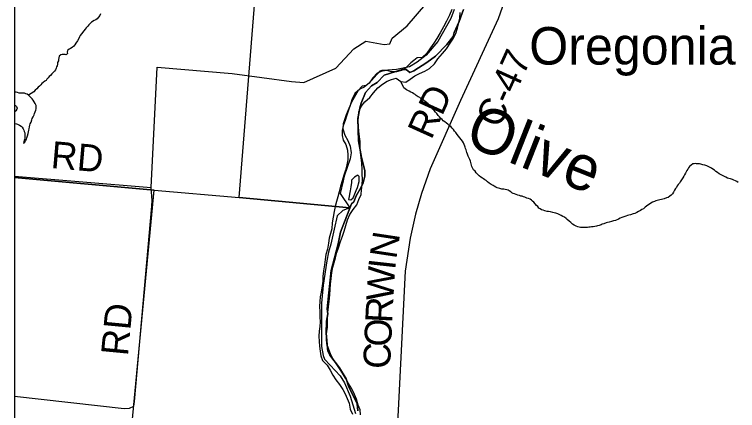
# Model space of a CAD drawing. Extents: x 0.4 to 34.4, y -2.1 to 19.9.
# Drawn here: x 3 to 4.522, y 15.102 to 15.936 of the extents above; entities that cross this region are included whole.
import ezdxf

# ---------------------------------------------------------------- set-up
doc = ezdxf.new("R2010")
doc.units = 0
for name, color, linetype in [('GM_X_County', 7, 'Continuous'), ('GM_X_County_Road', 7, 'Continuous'), ('GM_X_County_Road_Text', 7, 'Continuous'), ('GM_X_Major_River', 7, 'Continuous'), ('GM_X_Minor_Lake', 7, 'Continuous'), ('GM_X_Minor_River', 7, 'Continuous'), ('GM_X_Minor_River_Text', 7, 'Continuous'), ('GM_X_Section', 7, 'Continuous'), ('GM_X_Township', 7, 'Continuous'), ('GM_X_Township_Road', 7, 'Continuous'), ('GM_X_Township_Road_Text', 7, 'Continuous'), ('GM_X_Unincorporated_Text', 7, 'Continuous'), ('SH_Data', 7, 'Continuous')]:
    doc.layers.add(name, color=color, linetype=linetype)

msp = doc.modelspace()

# ---------------------------------------------------------------- linework, layer by layer
at = {"layer": 'GM_X_County'}
msp.add_lwpolyline([(9.8001, 15.3423), (9.8001, 18.8357), (3.0001, 18.8357), (3.0001, 12.0357), (9.5074, 12.0357)], dxfattribs=at)
at = {"layer": 'GM_X_County_Road'}
msp.add_lwpolyline([(4.0921, 16.025), (4.075, 16.0392), (4.0559, 16.0588), (4.042, 16.007), (4.0308, 15.9623), (4.0179, 15.9268), (3.9392, 15.755), (3.8752, 15.6108), (3.8571, 15.559), (3.8445, 15.5155), (3.8329, 15.4647), (3.8225, 15.3954), (3.798, 14.9078), (3.7927, 14.8467), (3.7874, 14.8168), (3.7683, 14.7707), (3.7416, 14.7273), (3.683, 14.6568)], dxfattribs=at)
at = {"layer": 'GM_X_Major_River'}
for points in [[(3.6597, 15.3086), (3.6614, 15.3207), (3.6623, 15.3321), (3.664, 15.3457), (3.6646, 15.3579), (3.6655, 15.3681), (3.6664, 15.3802), (3.6682, 15.3927), (3.6702, 15.4037), (3.673, 15.4135), (3.6758, 15.4237), (3.6787, 15.435), (3.6827, 15.4467), (3.6866, 15.4581), (3.6906, 15.4694), (3.6942, 15.4796), (3.6978, 15.4916), (3.7014, 15.5037), (3.7061, 15.515), (3.7131, 15.5252), (3.7205, 15.5353), (3.7252, 15.5462), (3.7299, 15.5568), (3.7308, 15.567), (3.7317, 15.5776), (3.7323, 15.589), (3.7321, 15.5996), (3.7322, 15.6098), (3.7313, 15.6231), (3.7296, 15.6342), (3.7282, 15.6463), (3.7277, 15.6585), (3.7274, 15.6687), (3.7265, 15.6786), (3.7251, 15.6904), (3.7245, 15.6999), (3.7236, 15.712), (3.7246, 15.7306), (3.7297, 15.7419), (3.7375, 15.752), (3.7478, 15.761), (3.7556, 15.7711), (3.7649, 15.7812), (3.7748, 15.7894), (3.7844, 15.7953), (3.794, 15.7989), (3.8035, 15.8014), (3.8136, 15.7944), (3.8235, 15.7932), (3.8331, 15.7998), (3.8431, 15.8069), (3.8526, 15.8113), (3.8637, 15.8164), (3.874, 15.8223), (3.8841, 15.832), (3.8914, 15.8425), (3.9007, 15.8534), (3.9092, 15.8631), (3.9174, 15.8755), (3.924, 15.8857), (3.9291, 15.8954), (3.9327, 15.9068), (3.9351, 15.9185), (3.9372, 15.9283), (3.9381, 15.9401)], [(3.9207, 15.946), (3.9156, 15.934), (3.9097, 15.9215), (3.9031, 15.9095), (3.8961, 15.8971)], [(3.8961, 15.8971), (3.8894, 15.8854), (3.8828, 15.8757), (3.8758, 15.8652), (3.8677, 15.8543), (3.8581, 15.8453), (3.8478, 15.8444), (3.8408, 15.8387), (3.8344, 15.834), (3.824, 15.8235), (3.8144, 15.8176), (3.8041, 15.8151), (3.7938, 15.8152), (3.7836, 15.8181), (3.7738, 15.8167), (3.7634, 15.8119), (3.7545, 15.8022), (3.7468, 15.7909), (3.7364, 15.7831), (3.7269, 15.7787), (3.7168, 15.7694), (3.7102, 15.7562), (3.7066, 15.7441), (3.7034, 15.7343), (3.6998, 15.7238), (3.6962, 15.7128), (3.6919, 15.7015), (3.6895, 15.6917), (3.6897, 15.6811), (3.6922, 15.6715), (3.6974, 15.662), (3.701, 15.6505), (3.7016, 15.6395), (3.7018, 15.6297), (3.6997, 15.6191), (3.6969, 15.6081), (3.6933, 15.5976), (3.6897, 15.5859), (3.6865, 15.5745), (3.6833, 15.5624), (3.6809, 15.5518), (3.6777, 15.542), (3.6748, 15.5315), (3.6732, 15.5209), (3.6707, 15.5091), (3.669, 15.4974), (3.6681, 15.4849), (3.6656, 15.4751), (3.6628, 15.4653), (3.6608, 15.4543), (3.6587, 15.4418), (3.6558, 15.4305), (3.6538, 15.4203), (3.6525, 15.4089), (3.6507, 15.396), (3.6494, 15.3843), (3.6489, 15.3748), (3.6476, 15.3646), (3.6455, 15.3513), (3.6435, 15.3415), (3.6429, 15.3316), (3.6424, 15.321), (3.6426, 15.3097), (3.6428, 15.299), (3.6434, 15.2888), (3.6429, 15.2793), (3.6416, 15.2691), (3.6407, 15.2588), (3.6413, 15.2478), (3.6422, 15.2376), (3.6436, 15.2269), (3.645, 15.2174), (3.6486, 15.2075), (3.6583, 15.1979), (3.6646, 15.1872), (3.6702, 15.1764), (3.6768, 15.1669), (3.6843, 15.1569), (3.691, 15.1469), (3.6961, 15.1373), (3.7005, 15.1274), (3.7045, 15.1175), (3.707, 15.1053), (3.7114, 15.0946)], [(3.7226, 15.5979), (3.716, 15.5934), (3.7098, 15.5868), (3.7094, 15.5821), (3.7081, 15.5727), (3.7069, 15.5643), (3.7056, 15.5579), (3.7044, 15.5526), (3.7035, 15.5462), (3.7081, 15.5454), (3.7127, 15.5502), (3.7151, 15.5551)], [(3.7151, 15.5551), (3.719, 15.5653), (3.7221, 15.5713), (3.7254, 15.5842), (3.7255, 15.5948), (3.7226, 15.5979)], [(3.7281, 15.0932), (3.7275, 15.1035), (3.7238, 15.1138), (3.7199, 15.126), (3.7158, 15.1363), (3.7103, 15.1481), (3.7033, 15.1592), (3.6966, 15.1703), (3.6907, 15.1811), (3.684, 15.1906), (3.6774, 15.201), (3.6703, 15.2117), (3.6651, 15.2213), (3.6615, 15.2308), (3.6579, 15.243), (3.6569, 15.2533), (3.6571, 15.2639), (3.6588, 15.2779), (3.659, 15.2878), (3.6587, 15.2984), (3.6597, 15.3086)]]:
    msp.add_lwpolyline(points, dxfattribs=at)
at = {"layer": 'GM_X_Minor_Lake'}
for points in [[(3.0299, 15.7662), (3.0269, 15.7682), (3.0243, 15.769), (3.0216, 15.7698), (3.0182, 15.7702), (3.0152, 15.7703), (3.0125, 15.7703), (3.0098, 15.7704), (3.0064, 15.7712), (3.0034, 15.772), (3.0007, 15.7725), (3.0001, 15.7726)], [(3.0001, 15.7062), (3.0008, 15.7063), (3.0042, 15.7054), (3.0068, 15.7046), (3.0106, 15.703), (3.014, 15.7007), (3.0166, 15.6984), (3.0181, 15.6953), (3.0195, 15.6922), (3.0206, 15.6895), (3.0217, 15.6868), (3.022, 15.6842), (3.0219, 15.6815), (3.0222, 15.6758), (3.0214, 15.6724), (3.0201, 15.6678), (3.0189, 15.6648), (3.022, 15.667), (3.0236, 15.6701), (3.0256, 15.6731), (3.0264, 15.6765), (3.0276, 15.6806), (3.0289, 15.6856), (3.0297, 15.689), (3.0306, 15.692), (3.0314, 15.695), (3.0319, 15.6996), (3.0327, 15.703), (3.0332, 15.7057), (3.0351, 15.709), (3.0368, 15.714), (3.0376, 15.717), (3.0392, 15.7204), (3.0416, 15.7249), (3.042, 15.7276), (3.0436, 15.731), (3.0449, 15.7347), (3.0457, 15.7374), (3.0457, 15.7401), (3.0455, 15.7443), (3.044, 15.7481), (3.0418, 15.7519), (3.0396, 15.7554), (3.0374, 15.7585), (3.0299, 15.7662)], [(3.0001, 15.7452), (3.002, 15.7443), (3.0046, 15.742), (3.0057, 15.7389), (3.0049, 15.7362), (3.0033, 15.7328), (3.0006, 15.731), (3.0001, 15.7308)]]:
    msp.add_lwpolyline(points, dxfattribs=at)
at = {"layer": 'GM_X_Minor_River'}
for points in [[(3.1813, 15.9373), (3.1801, 15.9339), (3.177, 15.9298), (3.1742, 15.9268), (3.1711, 15.9246), (3.168, 15.9228), (3.1626, 15.9194), (3.1599, 15.9172), (3.1568, 15.9138), (3.1544, 15.9108), (3.1509, 15.9078), (3.1489, 15.9048), (3.1458, 15.9011), (3.1415, 15.8947), (3.1387, 15.8913), (3.1371, 15.8887), (3.1355, 15.8853), (3.1328, 15.88), (3.1292, 15.8755), (3.1272, 15.8721), (3.1249, 15.8691), (3.1218, 15.8661), (3.1179, 15.8639), (3.1152, 15.8625), (3.1117, 15.8602), (3.1113, 15.8561), (3.1116, 15.8534), (3.1092, 15.8508), (3.1066, 15.8512), (3.1031, 15.8513), (3.1005, 15.8513), (3.0974, 15.851), (3.0943, 15.848), (3.0934, 15.8442), (3.093, 15.8408), (3.0925, 15.8381), (3.0909, 15.8344), (3.0905, 15.8309), (3.0897, 15.8279), (3.0888, 15.8253), (3.088, 15.8226), (3.0864, 15.8192), (3.0844, 15.8166), (3.0817, 15.8136), (3.079, 15.811), (3.0759, 15.8076), (3.0731, 15.805), (3.0712, 15.8024), (3.0684, 15.7998), (3.0668, 15.7971), (3.0638, 15.7953), (3.0606, 15.7927), (3.0579, 15.7904), (3.0556, 15.7878), (3.0525, 15.7852), (3.0501, 15.7826), (3.047, 15.7796), (3.0439, 15.7766), (3.0408, 15.7733), (3.0299, 15.7662)], [(3.9093, 15.7071), (3.9056, 15.7095), (3.9026, 15.7118), (3.9, 15.7149), (3.8974, 15.7168), (3.8944, 15.7203), (3.8922, 15.723), (3.8888, 15.7273), (3.8862, 15.7304), (3.8836, 15.7335), (3.881, 15.7362), (3.8777, 15.7404), (3.8758, 15.7431), (3.8732, 15.7447), (3.8706, 15.7478), (3.8676, 15.7505), (3.8646, 15.7528), (3.8612, 15.7552), (3.8582, 15.7571), (3.8556, 15.7587), (3.853, 15.7607), (3.85, 15.7626), (3.8458, 15.7654), (3.8432, 15.7673), (3.8406, 15.7689), (3.8376, 15.7708), (3.8342, 15.7724), (3.8308, 15.7744), (3.8281, 15.7759), (3.8251, 15.7771), (3.8221, 15.7795), (3.8195, 15.7814), (3.8136, 15.7944)], [(4.1885, 15.4881), (4.1858, 15.4889), (4.1821, 15.4905), (4.1783, 15.4925), (4.1749, 15.4948), (4.1708, 15.498), (4.1674, 15.5007), (4.1637, 15.5042), (4.1611, 15.5065), (4.1577, 15.5089), (4.1543, 15.5108), (4.1505, 15.5128), (4.1464, 15.5148), (4.1437, 15.516), (4.1396, 15.5176), (4.1358, 15.5184), (4.1331, 15.5192), (4.1286, 15.5201), (4.124, 15.5209), (4.121, 15.5213), (4.1164, 15.5222), (4.1126, 15.5238), (4.1096, 15.525), (4.1066, 15.5265), (4.104, 15.5285), (4.1014, 15.5316), (4.0988, 15.5339), (4.0958, 15.5374), (4.0932, 15.5405), (4.0906, 15.5428), (4.088, 15.5448), (4.0853, 15.5471), (4.0819, 15.5483), (4.0785, 15.5495), (4.0744, 15.5511), (4.0713, 15.5523), (4.0687, 15.5531), (4.066, 15.5535), (4.063, 15.5547), (4.0596, 15.5556), (4.0562, 15.5568), (4.0528, 15.558), (4.0498, 15.5592), (4.0471, 15.5604), (4.0445, 15.5623), (4.0415, 15.5643), (4.0389, 15.5658), (4.0362, 15.567), (4.0332, 15.5675), (4.0301, 15.5679), (4.0256, 15.5684), (4.0214, 15.5692), (4.0187, 15.57), (4.0161, 15.5712), (4.0131, 15.5724), (4.0101, 15.5747), (4.0074, 15.5759), (4.0037, 15.5783), (3.9995, 15.581), (3.9958, 15.5838), (3.9928, 15.5861), (3.9902, 15.5877), (3.9875, 15.5896), (3.9849, 15.5912), (3.9819, 15.5935), (3.9785, 15.5962), (3.9755, 15.599), (3.9718, 15.6028), (3.97, 15.6059), (3.9666, 15.609), (3.964, 15.6133), (3.963, 15.6159), (3.9619, 15.6186), (3.9612, 15.6213), (3.9609, 15.624), (3.9598, 15.627), (3.9583, 15.6305), (3.9573, 15.6332), (3.9551, 15.6374), (3.9536, 15.6416), (3.9522, 15.6451), (3.9515, 15.6481), (3.9508, 15.6508), (3.9497, 15.6535), (3.949, 15.6562), (3.9479, 15.6588), (3.9468, 15.6623), (3.945, 15.6654), (3.9428, 15.6688), (3.9402, 15.6727), (3.9376, 15.6765), (3.9347, 15.68), (3.9321, 15.6831), (3.9291, 15.6877), (3.9265, 15.6904), (3.9239, 15.6935), (3.9213, 15.6966), (3.9183, 15.6997), (3.9153, 15.7021), (3.912, 15.7048), (3.9093, 15.7071)], [(4.5114, 15.5884), (4.5072, 15.59), (4.5038, 15.5904), (4.5008, 15.5916), (4.497, 15.5936), (4.4944, 15.5948), (4.4906, 15.5968), (4.4872, 15.5983), (4.4834, 15.6007), (4.4801, 15.603), (4.4763, 15.6054), (4.4733, 15.6081), (4.4703, 15.6101), (4.4673, 15.612), (4.4647, 15.614), (4.4605, 15.616), (4.4571, 15.6175), (4.4533, 15.6184), (4.4492, 15.6196), (4.445, 15.6208), (4.4416, 15.6216), (4.4385, 15.6217), (4.4359, 15.6217), (4.4332, 15.6218), (4.4305, 15.6214), (4.4279, 15.6211), (4.4244, 15.6189), (4.4212, 15.6155), (4.4189, 15.6129), (4.4173, 15.6103), (4.4153, 15.6076), (4.4122, 15.602), (4.4106, 15.5982), (4.409, 15.5956), (4.4066, 15.5918), (4.4042, 15.5881), (4.4015, 15.5839), (4.3995, 15.5805), (4.3971, 15.5779), (4.3952, 15.5753), (4.3932, 15.5719), (4.3912, 15.5693), (4.3896, 15.5659), (4.3873, 15.5621), (4.3853, 15.5583), (4.3822, 15.5554), (4.3794, 15.5531), (4.376, 15.5509), (4.3725, 15.5498), (4.3675, 15.548), (4.3648, 15.5469), (4.3617, 15.5462), (4.3583, 15.5455), (4.3556, 15.5448), (4.3525, 15.5441), (4.3499, 15.5434), (4.3472, 15.5423), (4.3433, 15.5405), (4.3398, 15.5386), (4.3364, 15.5368), (4.3333, 15.5346), (4.3306, 15.5327), (4.3278, 15.5305), (4.3243, 15.5271), (4.3209, 15.5253), (4.3174, 15.5231), (4.3135, 15.5208), (4.3097, 15.519), (4.3058, 15.5172), (4.302, 15.5161), (4.297, 15.5143), (4.2931, 15.5132), (4.2904, 15.5125), (4.287, 15.5111), (4.2824, 15.5096), (4.2785, 15.5085), (4.2751, 15.5071), (4.2716, 15.5049), (4.2651, 15.5023), (4.2612, 15.5013), (4.2566, 15.4998), (4.252, 15.4988), (4.2482, 15.4977), (4.2455, 15.497), (4.2409, 15.4955), (4.2374, 15.4945), (4.2347, 15.493), (4.2309, 15.4915), (4.2274, 15.4908), (4.2248, 15.4905), (4.2213, 15.4898), (4.2182, 15.4891), (4.2148, 15.4888), (4.2121, 15.4885), (4.2087, 15.4881), (4.206, 15.4878), (4.2018, 15.4875), (4.1984, 15.4876), (4.1946, 15.4876), (4.1915, 15.4877), (4.1885, 15.4881)], [(4.5231, 15.5825), (4.5204, 15.584), (4.5178, 15.586), (4.5144, 15.5872), (4.5114, 15.5884)]]:
    msp.add_lwpolyline(points, dxfattribs=at)
at = {"layer": 'GM_X_Section'}
for p, q in [((3.0001, 16.8828), (3.0001, 15.5924)), ((3.0001, 15.5924), (3.0001, 14.5041))]:
    msp.add_line(p, q, dxfattribs=at)
for points in [[(3.0001, 15.5924), (3.2941, 15.5661), (3.4729, 15.5505), (3.5755, 16.8348), (3.0001, 16.8828)], [(3.9259, 15.9464), (3.9187, 15.9275), (3.891, 15.8788), (3.8663, 15.8501), (3.8478, 15.8352), (3.8318, 15.8257), (3.8044, 15.8201), (3.7862, 15.8185), (3.7733, 15.818), (3.7691, 15.8162), (3.7575, 15.8031), (3.7467, 15.7915), (3.7402, 15.786), (3.7319, 15.7846), (3.7234, 15.776), (3.7093, 15.7513), (3.6982, 15.7246), (3.6918, 15.7054), (3.6913, 15.6952), (3.6952, 15.6819), (3.7019, 15.6708), (3.7066, 15.6586), (3.709, 15.6449), (3.7065, 15.6317), (3.6941, 15.5952), (3.692, 15.5858), (3.6859, 15.5593), (3.7058, 15.5291), (3.4729, 15.5505), (3.5755, 16.8348)], [(3.0001, 14.5041), (3.192, 14.4845), (3.2941, 15.5661), (3.0001, 15.5924)], [(3.192, 14.4845), (3.2941, 15.5661), (3.4729, 15.5505), (3.7058, 15.5291), (3.691, 15.5229), (3.679, 15.5117), (3.6732, 15.4838), (3.6662, 15.4521), (3.661, 15.4359), (3.6577, 15.4171), (3.65, 15.3661), (3.6463, 15.3286), (3.6464, 15.2877), (3.6466, 15.2374), (3.6497, 15.218), (3.653, 15.2107), (3.6649, 15.1977), (3.6853, 15.175), (3.6949, 15.1608), (3.7069, 15.1326), (3.7176, 15.096)]]:
    msp.add_lwpolyline(points, dxfattribs=at)
at = {"layer": 'GM_X_Township'}
msp.add_line((3.0001, 17.934), (3.0001, 12.5191), dxfattribs=at)
for points in [[(3.7227, 15.1017), (3.7217, 15.1162), (3.7031, 15.1537), (3.6982, 15.1687), (3.6842, 15.1919), (3.6638, 15.2187), (3.6598, 15.2273), (3.6587, 15.2335), (3.6562, 15.2648), (3.6568, 15.2903), (3.6598, 15.3061), (3.6584, 15.3163), (3.663, 15.3636), (3.6664, 15.3967), (3.6815, 15.4531), (3.6863, 15.4775), (3.7092, 15.5375), (3.7146, 15.5416), (3.7196, 15.5541), (3.73, 15.5726), (3.7338, 15.5816), (3.7372, 15.5953), (3.7376, 15.6075), (3.7303, 15.635), (3.7239, 15.6697), (3.7231, 15.7166), (3.7274, 15.7421), (3.7298, 15.749), (3.7393, 15.7718), (3.745, 15.7789), (3.7519, 15.7855), (3.7634, 15.7929), (3.7783, 15.808), (3.8162, 15.8197), (3.8243, 15.8196), (3.832, 15.8138), (3.8404, 15.8173), (3.8681, 15.8345), (3.8861, 15.8479), (3.9104, 15.8723), (3.9233, 15.8894), (3.9257, 15.8981), (3.9364, 15.921), (3.945, 15.9464)], [(3.945, 15.9464), (3.9364, 15.921), (3.9257, 15.8981), (3.9233, 15.8894), (3.9104, 15.8723), (3.8861, 15.8479), (3.8681, 15.8345), (3.8404, 15.8173), (3.832, 15.8138), (3.8243, 15.8196), (3.8162, 15.8197), (3.7783, 15.808), (3.7634, 15.7929), (3.7519, 15.7855), (3.745, 15.7789), (3.7393, 15.7718), (3.7298, 15.749), (3.7274, 15.7421), (3.7231, 15.7166), (3.7239, 15.6697), (3.7303, 15.635), (3.7376, 15.6075), (3.7372, 15.5953), (3.7338, 15.5816), (3.73, 15.5726), (3.7196, 15.5541), (3.7146, 15.5416), (3.7092, 15.5375), (3.6863, 15.4775), (3.6815, 15.4531), (3.6664, 15.3967), (3.663, 15.3636), (3.6584, 15.3163), (3.6598, 15.3061), (3.6568, 15.2903), (3.6562, 15.2648), (3.6587, 15.2335), (3.6598, 15.2273), (3.6638, 15.2187), (3.6842, 15.1919), (3.6982, 15.1687), (3.7031, 15.1537), (3.7217, 15.1162), (3.7227, 15.1017)]]:
    msp.add_lwpolyline(points, dxfattribs=at)
at = {"layer": 'GM_X_Township_Road'}
for points in [[(3.2879, 15.5719), (3.3003, 15.8252), (3.4582, 15.8115), (3.583, 15.7944), (3.6089, 15.7924), (3.6764, 15.8224), (3.7141, 15.8637), (3.74, 15.8793), (3.7779, 15.8728), (3.79, 15.8741), (3.7951, 15.8858), (3.8269, 15.9116), (3.8658, 15.9575), (3.8915, 16.013), (3.8998, 16.0717), (3.8814, 16.1816), (3.8825, 16.2162)], [(3.0001, 15.5957), (3.2879, 15.5719)], [(3.2889, 15.5324), (3.2899, 15.5446), (3.2879, 15.5719)], [(3.0001, 15.1325), (3.2312, 15.1066), (3.2425, 15.1076), (3.2516, 15.1118), (3.2526, 15.1216), (3.2889, 15.5324)]]:
    msp.add_lwpolyline(points, dxfattribs=at)
at = {"layer": 'SH_Data'}
msp.add_line((3.0001, 18.8357), (3.0001, 12.0357), dxfattribs=at)

# ---------------------------------------------------------------- texts
at = {"layer": 'GM_X_County_Road_Text'}
for s, height, rotation, p in [('C-47', 0.05682, 65.5735, (4.021, 15.6941)), ('RD', 0.05682, 65.6372, (3.8774, 15.6705)), ('N', 0.0568, 81.3485, (3.8037, 15.4196)), ('I', 0.0568, 83.7115, (3.8012, 15.397)), ('W', 0.0568, 86.5534, (3.7973, 15.332)), ('R', 0.0568, 87.2395, (3.795, 15.2856)), ('O', 0.0568, 87.2434, (3.7926, 15.2357)), ('C', 0.0568, 87.2395, (3.7904, 15.189))]:
    msp.add_text(s, height=height, rotation=rotation, dxfattribs=at).set_placement(p)
at = {"layer": 'GM_X_Minor_River_Text'}
msp.add_text('Olive', height=0.0947, rotation=338.4228, dxfattribs=at).set_placement((3.9443, 15.6628))
at = {"layer": 'GM_X_Township_Road_Text'}
for rotation, p in [(355.0719, (3.0755, 15.6127)), (84.5841, (3.2388, 15.2159))]:
    msp.add_text('RD', height=0.05682, rotation=rotation, dxfattribs=at).set_placement(p)
at = {"layer": 'GM_X_Unincorporated_Text'}
msp.add_text('Oregonia', height=0.07898, rotation=0, dxfattribs=at).set_placement((4.0835, 15.8303))

doc.saveas('drawing.dxf')
